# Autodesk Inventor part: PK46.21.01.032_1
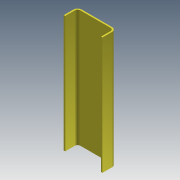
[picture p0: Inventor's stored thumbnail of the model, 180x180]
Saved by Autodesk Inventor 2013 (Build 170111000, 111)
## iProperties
Created: 2005-03
Part Number: PK46.21.01.032_1
Material: Steel, Mild
Document SubType Name: Sheet Metal
Designer: salex
Manufacturer: Standard
Standards Organization: Custom
Density: 7.86 g/cm^3
Sheet Metal Rule: Default
Author: salex
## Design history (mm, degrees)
node "ФлнОтгиб1"
body "Solid1"
sketch "Эскиз1"
  geometry: L1 (0, 0)-(0, 90); L2 (0, 90)-(260, 90); L3 (260, 90)-(260, 0)
  constraints: 6 end point, 2 parallel, 1 perpendicular, 1 vertical, 1 other
  dimensions: "d0" = 260 distance of L1.end L2.end; "d1" = 90 distance of L1.start L1.end
feature "Плакирование1" dims "d2" = 850, "d3" = 10 (= BendReliefWidth), "d5" = 20 (= MinimumRemnant), "d7" = 20 (= BendRadius), "d8" = 10, "Thickness" = 10
feature "Изгиб1" dims "d3" = 10 (= BendReliefWidth), "d4" = 5 (= BendReliefDepth), "d5" = 20 (= MinimumRemnant), "d6" = 20 (= BendRadius), "d7" = 20 (= BendRadius), "d8" = 10, "SeamGap" = 0.01, "Thickness" = 10
other parameters: "BendRadius" = 20, "BendReliefDepth" = 5 (= 0.5 x Thickness)
